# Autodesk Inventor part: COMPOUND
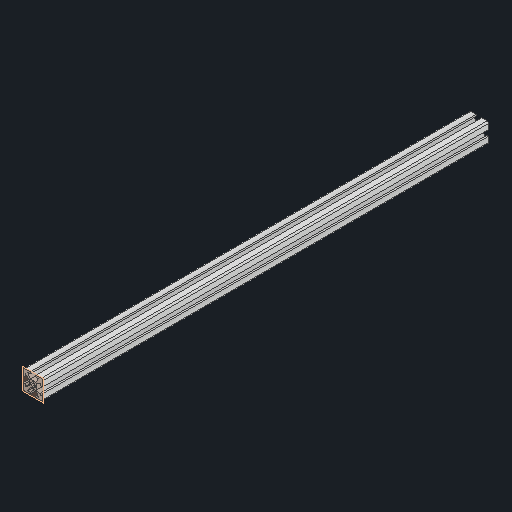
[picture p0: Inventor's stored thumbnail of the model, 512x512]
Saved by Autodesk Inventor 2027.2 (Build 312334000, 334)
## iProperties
Created: 2026-11
Part Number: COMPOUND
Material: Genérico
Document SubType Name: Modeling
Designer: Usuario
Density: 1 g/cm^3
Appearance: Valor por defecto
Author: Usuario
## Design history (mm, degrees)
feature "Base1"
node "Plano de trabajo1"
sketch "Boceto1"
  geometry: L1 (-50, -50)-(50, -50); L2 (50, -50)-(50, 50); L3 (50, 50)-(-50, 50); L4 (-50, 50)-(-50, -50)
  constraints: 8 end point, 2 parallel, 1 horizontal, 1 perpendicular
extrude "Extrusión1" cut sketch "Boceto1" distance "d1" = 50; taper "d2" = 0 deg
node "Sólido1"
